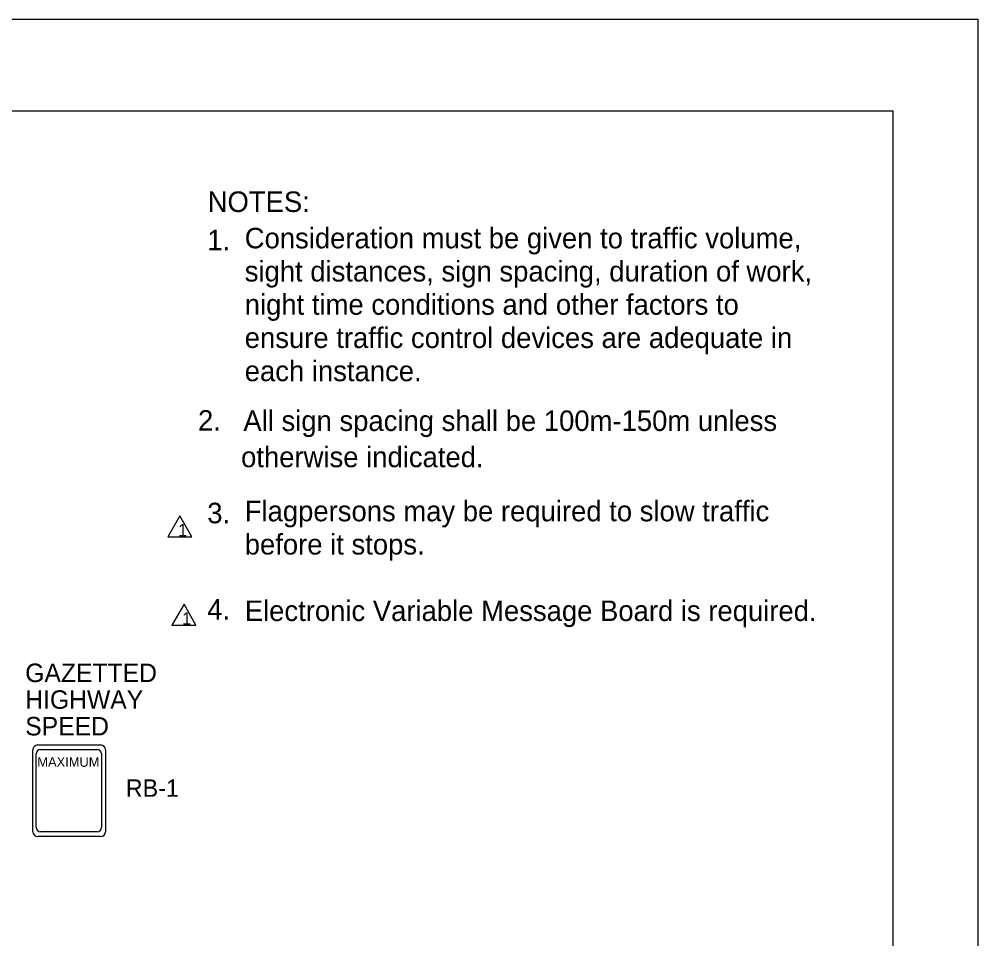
# Model space of a CAD drawing. Extents: x 1361 to 1577, y 123 to 402.
# Drawn here: x 1464.1 to 1577.1, y 293.6 to 402.1 of the extents above; entities that cross this region are included whole.
import ezdxf

# ---------------------------------------------------------------- set-up
doc = ezdxf.new("R2010")
doc.units = 0
for name, color, linetype in [('Level 1', 7, 'Continuous'), ('Level 10', 7, 'Continuous'), ('Level 44', 7, 'Continuous'), ('Level 60', 7, 'Continuous')]:
    doc.layers.add(name, color=color, linetype=linetype)

msp = doc.modelspace()

# ---------------------------------------------------------------- linework, layer by layer
at = {"layer": 'Level 1'}
for points in [[(1483.04, 343.52), (1481.62, 341.05), (1484.46, 341.05)], [(1483.52, 333.09), (1482.1, 330.62), (1484.93, 330.62)]]:
    msp.add_lwpolyline(points, close=True, dxfattribs=at)
at = {"layer": 'Level 44'}
for p, q in [((1466.28, 316.5), (1473.69, 316.5)), ((1465.71, 306.27), (1465.71, 315.93)), ((1466.09, 306.76), (1466.09, 315.45)), ((1466.61, 315.96), (1473.28, 315.96)), ((1473.79, 315.45), (1473.79, 306.76)), ((1474.26, 315.93), (1474.26, 306.27)), ((1466.09, 306.76), (1466.09, 306.76)), ((1465.71, 306.27), (1465.71, 306.27)), ((1473.69, 305.7), (1466.28, 305.7)), ((1466.41, 305.93), (1466.41, 305.93)), ((1473.28, 306.24), (1466.61, 306.24))]:
    msp.add_line(p, q, dxfattribs=at)
for centre, radius, start, end in [((1466.28, 315.93), 0.572, 90, 180), ((1473.69, 315.93), 0.572, 360, 90), ((1466.61, 315.45), 0.514, 90, 180), ((1473.27, 315.45), 0.514, 360, 90), ((1466.61, 306.76), 0.514, 180, 270), ((1473.27, 306.76), 0.514, 270, 360), ((1466.28, 306.27), 0.572, 180, 270), ((1473.69, 306.27), 0.572, 270, 360)]:
    msp.add_arc(centre, radius, start, end, dxfattribs=at)
at = {"layer": 'Level 60'}
for points in [[(1361.11, 402.1), (1577.11, 402.1), (1577.11, 123.1), (1361.11, 123.1)], [(1380.24, 391.29), (1567.11, 391.29), (1567.11, 133.91), (1380.24, 133.91)]]:
    msp.add_lwpolyline(points, close=True, dxfattribs=at)

# ---------------------------------------------------------------- texts
at = {"layer": 'Level 1'}
for p in [(1482.82, 341.11), (1483.29, 330.68)]:
    msp.add_text('1', height=1.45, rotation=360, dxfattribs=at).set_placement(p)
at = {"layer": 'Level 10'}
for s, height, p in [('NOTES:', 2.419, (1486.31, 379.36)), ('Consideration must be given to traffic volume,', 2.419, (1490.68, 375.07)), ('1.', 2.419, (1486.26, 374.84)), ('sight distances, sign spacing, duration of work,', 2.419, (1490.68, 371.16)), ('night time conditions and other factors to', 2.419, (1490.68, 367.24)), ('ensure traffic control devices are adequate in', 2.419, (1490.68, 363.32)), ('each instance.', 2.419, (1490.68, 359.4)), ('All sign spacing shall be 100m-150m unless', 2.419, (1490.52, 353.53)), ('2.', 2.419, (1485.17, 353.57)), ('otherwise indicated.', 2.419, (1490.25, 349.26)), ('3.', 2.419, (1486.26, 342.65)), ('Flagpersons may be required to slow traffic ', 2.419, (1490.68, 342.88)), ('before it stops.', 2.419, (1490.68, 338.96)), ('4.', 2.419, (1486.26, 331.28)), ('Electronic Variable Message Board is required.', 2.419, (1490.68, 331.12)), ('GAZETTED', 2.177, (1464.8, 323.92)), ('HIGHWAY', 2.177, (1464.8, 320.77)), ('SPEED', 2.177, (1464.8, 317.63))]:
    msp.add_text(s, height=height, dxfattribs=at).set_placement(p)
msp.add_text('RB-1', height=2.057, rotation=360, dxfattribs=at).set_placement((1476.65, 310.39))
at = {"layer": 'Level 44'}
msp.add_text('MAXIMUM', height=1.133, rotation=360, dxfattribs=at).set_placement((1466.23, 313.93))

doc.saveas('drawing.dxf')
